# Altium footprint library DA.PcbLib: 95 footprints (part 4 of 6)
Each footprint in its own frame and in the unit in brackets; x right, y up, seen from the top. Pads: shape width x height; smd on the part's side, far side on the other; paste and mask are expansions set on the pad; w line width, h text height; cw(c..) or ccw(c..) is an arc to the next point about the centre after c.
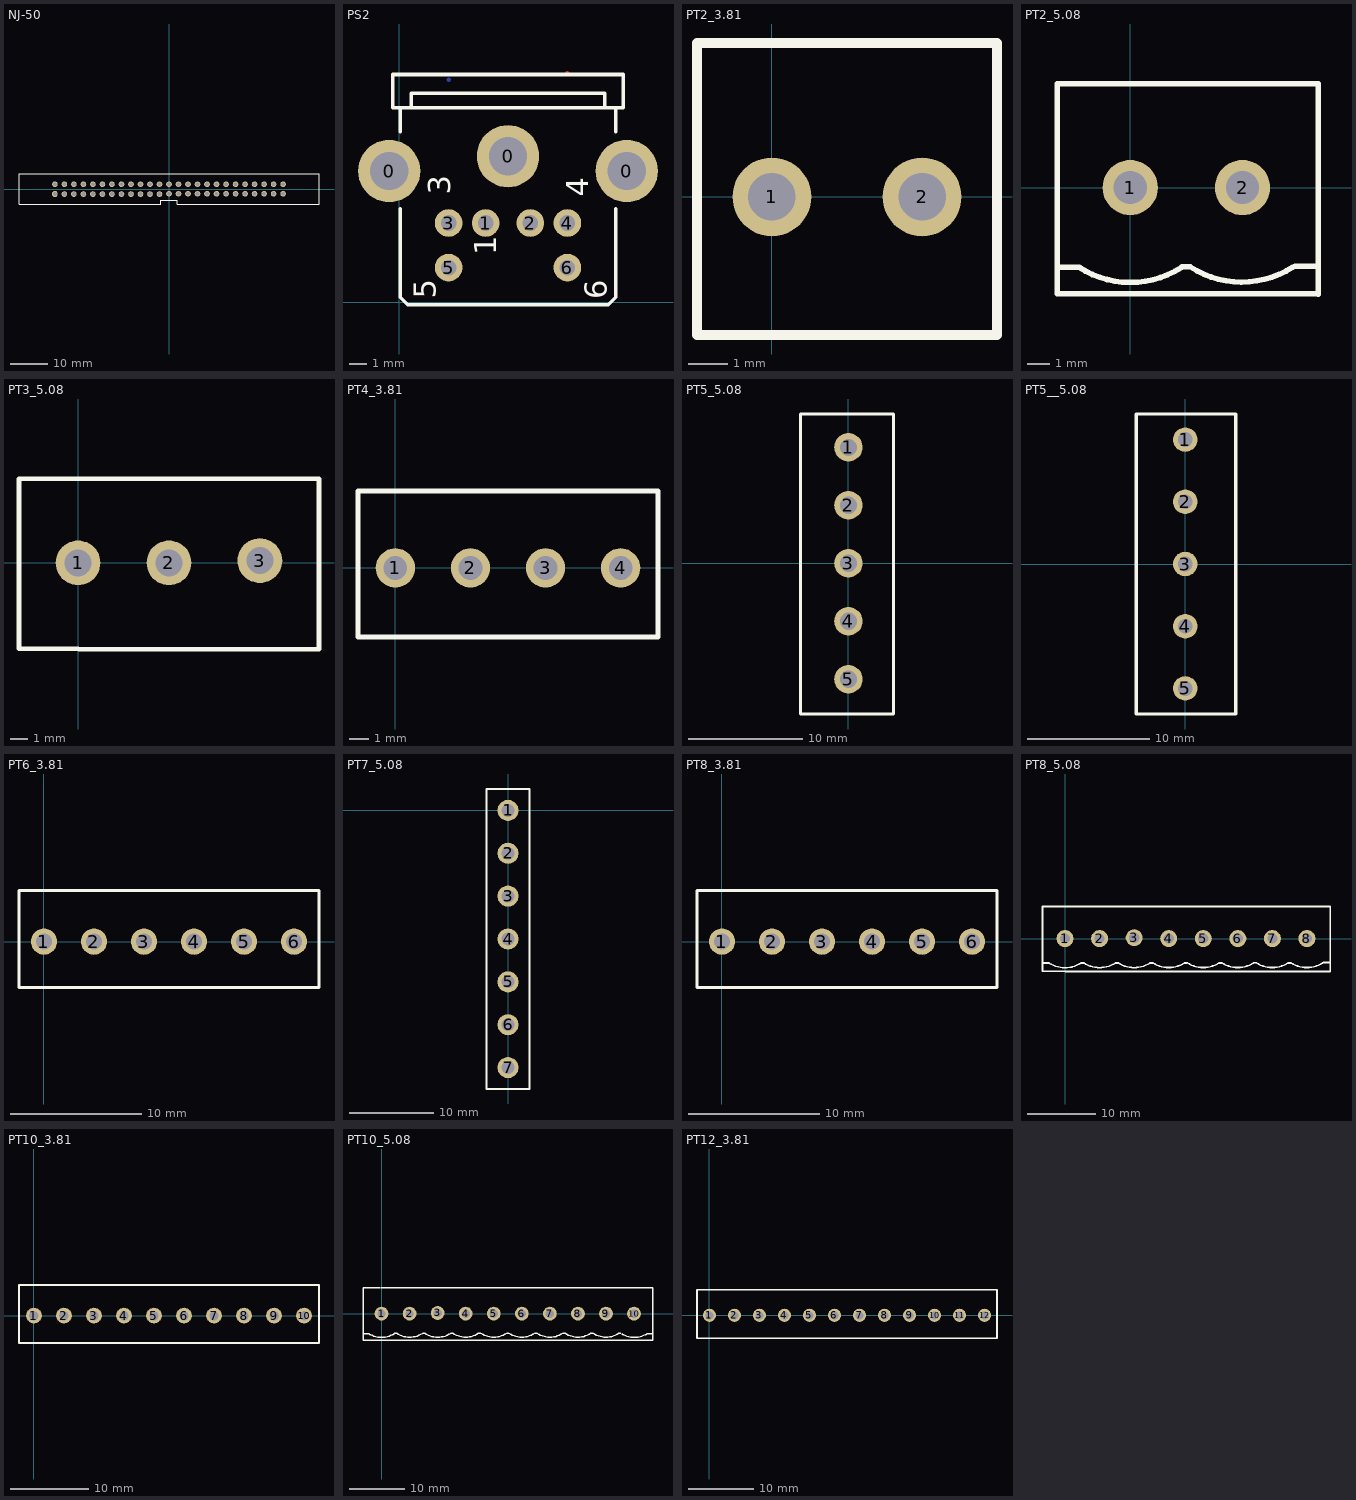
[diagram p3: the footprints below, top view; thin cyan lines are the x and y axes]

## NJ-50 [mm]
pads (50):
  oct 1.5x1.5 hole 1: 1(-30.48,-1.346)
  round 1.5 hole 1: 2(-30.48,1.27) 3(-27.94,-1.346) 4(-27.94,1.27) 5(-25.4,-1.346) 6(-25.4,1.27) 7(-22.86,-1.346) 8(-22.86,1.27) 9(-20.32,-1.346) 10(-20.32,1.27) 11(-17.78,-1.346) 12(-17.78,1.27) 13(-15.24,-1.346) 14(-15.24,1.27) 15(-12.7,-1.346) 16(-12.7,1.27) 17(-10.16,-1.346) 18(-10.16,1.27) 19(-7.62,-1.346) 20(-7.62,1.27) 21(-5.08,-1.346) 22(-5.08,1.27) 23(-2.54,-1.346) 24(-2.54,1.27) 25(0,-1.27) 26(0,1.27) 27(2.54,-1.27) 28(2.54,1.27) 29(5.08,-1.27) 30(5.08,1.27) 31(7.62,-1.27) 32(7.62,1.27) 33(10.16,-1.27) 34(10.16,1.27) 35(12.7,-1.27) 36(12.7,1.27) 37(15.24,-1.27) 38(15.24,1.27) 39(17.78,-1.27) 40(17.78,1.27) 41(20.32,-1.27) 42(20.32,1.27) 43(22.86,-1.27) 44(22.86,1.27) 45(25.4,-1.27) 46(25.4,1.27) 47(27.94,-1.27) 48(27.94,1.27) 49(30.48,-1.27) 50(30.48,1.27)
Top Overlay:
  lines w0.15: -2.15,-4.066 -2.15,-2.979 2.15,-2.979 2.15,-4.1
  lines w0.254: -2.15,-4.066 -2.184,-4.1 -40.08,-4.1 -40.08,4.1 40.08,4.1 40.08,-4.1 2.15,-4.1

## PCBComponent_1 [mm]

## PS2 [mil]
pads (9):
  round 140 hole 86: 0(-22.67,294.67) 0(244,328) 0(510.67,294.67)
  round 62 hole 35: 1(194,178) 2(294,178) 3(110.67,178) 4(377.33,178) 5(110.67,78) 6(377.33,78)
Top Layer:
  lines w10: 377,514 377.33,513.67
Bottom Layer:
  lines w10: 110.67,499.67 111,500 ; 376.33,77 377.33,78
Top Overlay:
  lines w8: 2.33,209.5 2.33,11.33 19,-5.33 469,-5.33 485.67,11.33 485.67,209.5 ; 2.33,382.72 2.33,436.33 ; 485.67,382.72 485.67,436.33 ; 27.33,436.33 460.67,436.33 ; 27.33,436.33 -14.33,436.33 -14.33,511.33 502.33,511.33 502.33,436.33 460.67,436.33 ; 27.33,436.33 27.33,469.67 460.67,469.67 460.67,436.33
  text "1" at 217.43,105.9 h50
  text "3" at 114.77,241.9 h50
  text "4" at 424.1,236.57 h50
  text "6" at 465.43,7.24 h50
  text "5" at 81.43,8.57 h50

## PT2_3.81 [mm]
pads (2):
  round 2 hole 1.2: 1(0,0) 2(3.81,0)
Top Overlay:
  lines w0.254: -1.9,-3.5 -1.9,3.9 5.71,3.9 5.71,-3.5 -1.595,-3.5 -1.9,-3.5

## PT2_5.08 [mm]
pads (2):
  round 2.5 hole 1.5: 1(0,0) 2(5.08,0)
Top Overlay:
  lines w0.254: -3.3,-3.596 -2.332,-3.596 ccw(c0.001,-0.024) 2.312,-3.61 ; -3.3,-0.3 -3.3,4.7 -0.2,4.7 ; -3.3,1.2 -3.3,0 -3.3,-2.7 -3.3,-4.8 0,-4.8 8.483,-4.8 8.509,-4.826 8.509,-1.111 8.509,4.7 -0.1,4.7 ; 2.34,-3.582 2.711,-3.582 ccw(c5.044,-0.01) 7.355,-3.596 ; 7.456,-3.556 8.382,-3.556

## PT3_5.08 [mm]
pads (3):
  round 2.5 hole 1.5: 1(0,0) 2(5.08,0) 3(10.16,0.127)
Top Overlay:
  lines w0.254: -3.3,-0.3 -3.3,4.7 -0.2,4.7 ; -3.3,1.2 -3.3,0 -3.3,-2.7 -3.3,-4.8 0,-4.8 0.026,-4.826 13.462,-4.826 13.462,4.7 -0.1,4.7

## PT4_3.81 [mm]
pads (4):
  round 2 hole 1.2: 1(0,0) 2(3.81,0) 3(7.62,0) 4(11.43,0)
Top Overlay:
  lines w0.254: -1.9,-3.5 -1.595,-3.5 13.33,-3.5 13.33,3.9 -1.9,3.9 -1.9,-3.5

## PT5_5.08 [mm]
pads (5):
  round 2.5 hole 1.5: 1(0,10.16) 2(0,5.08) 3(0,0) 4(0,-5.08) 5(0,-10.16)
Top Overlay:
  lines w0.254: -4.191,-13.208 -4.191,13.081 3.937,13.081 3.937,-13.208 -4.191,-13.208

## PT5__5.08 [mm]
pads (5):
  round 2 hole 1.2: 1(0,10.16) 2(0,5.08) 3(0,0) 4(0,-5.08) 5(0,-10.16)
Top Overlay:
  lines w0.254: 4,-12.25 -4,-12.25 -4,12.25 4,12.25 ; 4.128,-12.25 4.128,12.25

## PT6_3.81 [mm]
pads (6):
  round 2 hole 1.2: 1(0,0) 2(3.81,0) 3(7.62,0) 4(11.43,0) 5(15.24,0) 6(19.05,0)
Top Overlay:
  lines w0.254: 20.879,3.9 -1.9,3.9 -1.9,-3.5 -1.595,-3.5 20.95,-3.5 20.95,3.9

## PT7_5.08 [mm]
pads (7):
  round 2.5 hole 1.5: 1(0,0) 2(0,-5.08) 4(0,-15.24) 5(0,-20.32) 6(0,-25.4) 7(0,-30.48)
  round 2.5 hole 1.5 paste+0: 3(0,-10.16)
Top Overlay:
  lines w0.254: -2.54,-33.02 2.54,-33.02 2.54,2.54 -2.54,2.54 -2.54,-33.02

## PT8_3.81 [mm]
pads (6):
  round 2 hole 1.2: 1(0,0) 2(3.81,0) 3(7.62,0) 4(11.43,0) 5(15.24,0) 6(19.05,0)
Top Overlay:
  lines w0.254: -1.9,-3.5 -1.595,-3.5 20.95,-3.5 20.95,3.9 -1.9,3.9 -1.9,-3.5

## PT8_5.08 [mm]
pads (8):
  round 2.5 hole 1.5: 1(0,0) 2(5.08,0) 3(10.16,0.127) 4(15.24,0) 5(20.32,0) 6(25.4,0) 7(30.48,0) 8(35.56,0)
Top Overlay:
  lines w0.254: -3.3,-3.596 -2.332,-3.596 ccw(c0.001,-0.024) 2.312,-3.61 ; -3.3,-0.3 -3.3,4.7 -0.2,4.7 ; -3.3,1.2 -3.3,0 -3.3,-2.7 -3.3,-4.8 0,-4.8 0.026,-4.826 38.989,-4.826 38.989,4.674 ; -0.1,4.7 38.989,4.7 ; 2.34,-3.582 2.711,-3.582 ; 2.747,-3.582 ccw(c5.08,-0.01) 7.391,-3.596 ; 7.42,-3.582 7.791,-3.582 ; 7.827,-3.582 ccw(c10.16,-0.01) 12.471,-3.596 ; 12.5,-3.582 12.871,-3.582 ; 12.907,-3.572 ccw(c15.24,0) 17.551,-3.586 ; 17.529,-3.582 17.9,-3.582 ; 17.987,-3.572 ccw(c20.32,0) 22.631,-3.586 ; 22.685,-3.582 23.056,-3.582 ; 23.067,-3.572 ccw(c25.4,0) 27.711,-3.586 ; 27.791,-3.557 28.162,-3.557 ; 28.147,-3.572 ccw(c30.48,0) 32.791,-3.586 ; 32.871,-3.582 33.242,-3.582 ; 33.227,-3.572 ccw(c35.56,0) 37.871,-3.586 ; 37.961,-3.531 38.887,-3.531

## PT10_3.81 [mm]
pads (10):
  round 2 hole 1.2: 1(0,0) 2(3.81,0) 3(7.62,0) 4(11.43,0) 5(15.24,0) 6(19.05,0) 7(22.86,0) 8(26.67,0) 9(30.48,0) 10(34.29,0)
Top Overlay:
  lines w0.254: -1.9,-3.5 -1.595,-3.5 36.19,-3.5 36.19,3.9 -1.9,3.9 -1.9,-3.5

## PT10_5.08 [mm]
pads (10):
  round 2.5 hole 1.5: 1(0,0) 2(5.08,0) 3(10.16,0.127) 4(15.24,0) 5(20.32,0) 6(25.4,0) 7(30.48,0) 8(35.56,0) 9(40.64,0) 10(45.72,0)
Top Overlay:
  lines w0.254: -3.3,-3.596 -2.332,-3.596 ccw(c0.001,-0.024) 2.312,-3.61 ; -3.3,-0.3 -3.3,4.7 -0.2,4.7 ; -3.3,1.2 -3.3,0 -3.3,-2.7 -3.3,-4.8 0,-4.8 0.026,-4.826 49.098,-4.826 49.098,4.649 49.047,4.7 -0.1,4.7 ; 2.34,-3.582 2.711,-3.582 ; 2.747,-3.582 ccw(c5.08,-0.01) 7.391,-3.596 ; 7.42,-3.582 7.791,-3.582 ; 7.827,-3.582 ccw(c10.16,-0.01) 12.471,-3.596 ; 12.5,-3.582 12.871,-3.582 ; 12.907,-3.572 ccw(c15.24,0) 17.551,-3.586 ; 17.529,-3.582 17.9,-3.582 ; 17.987,-3.572 ccw(c20.32,0) 22.631,-3.586 ; 22.685,-3.582 23.056,-3.582 ; 23.067,-3.572 ccw(c25.4,0) 27.711,-3.586 ; 27.791,-3.557 28.162,-3.557 ; 28.147,-3.572 ccw(c30.48,0) 32.791,-3.586 ; 32.871,-3.582 33.242,-3.582 ; 33.227,-3.572 ccw(c35.56,0) 37.871,-3.586 38.242,-3.586 ; 38.307,-3.572 ccw(c40.64,0) 42.951,-3.586 ; 42.961,-3.581 43.332,-3.581 ; 43.463,-3.597 ccw(c45.796,-0.025) 48.107,-3.611 49.033,-3.611

## PT12_3.81 [mm]
pads (12):
  round 2 hole 1.2: 1(0,0) 2(3.81,0) 3(7.62,0) 4(11.43,0) 5(15.24,0) 6(19.05,0) 7(22.86,0) 8(26.67,0) 9(30.48,0) 10(34.29,0) 11(38.1,0) 12(41.91,0)
Top Overlay:
  lines w0.254: -1.9,-3.5 -1.595,-3.5 43.81,-3.5 43.81,3.9 -1.9,3.9 -1.9,-3.5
